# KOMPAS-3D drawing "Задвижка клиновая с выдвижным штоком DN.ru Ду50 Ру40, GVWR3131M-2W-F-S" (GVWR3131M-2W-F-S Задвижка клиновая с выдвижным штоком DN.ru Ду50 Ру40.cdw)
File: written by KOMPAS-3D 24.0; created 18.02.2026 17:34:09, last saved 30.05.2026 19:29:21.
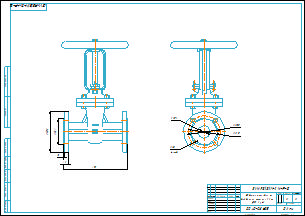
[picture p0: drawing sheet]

Document properties: art: D040-07875; Автор: R2D2; Форматы листов документа: A2; Полное имя файла: GVWR3131M-2W-F-S Задвижка клиновая с выдвижным штоком DN.ru Ду50 Ру40.m3d; Масса: 12; Наименование: Задвижка клиновая с выдвижным штоком DN.ru Ду50 Ру40; Количество листов документа: 1; Примечание: D040-08605

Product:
- Part/product: Задвижка клиновая с выдвижным штоком DN.ru Ду50 Ру40  | designation GVWR3131M-2W-F-S
    Масса: 12
    Раздел спецификации: Прочие изделия
    Примечание: D040-08605

Views: Вид 1, Спереди, Проекционный вид 2
Referenced files in E:\Работа\Зайцев\GVWR3131M-2W-F-S Задвижка клиновая с выдвижным штоком DN.ru Ду50-200 Ру63\DN50\: GVWR3131M-2W-F-S Задвижка клиновая с выдвижным штоком DN.ru Ду50 Ру63.m3d
Referenced files in E:\Работа\Зайцев\GVWR3131M-2W-F-S Задвижка клиновая с выдвижным штоком DN.ru Ду50-100 Ру40\исходные материалы\DN50\DN50\: GVWR3131M-2W-F-S Задвижка клиновая с выдвижным штоком DN.ru Ду50 Ру40.m3d
Referenced files in E:\Работа\Зайцев\Для компаса\: чертеж DN.ru.cdt
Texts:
  GVWR3131M-2W-F-S
  чертеж DN.ru.cdt
  Задвижка клиновая с
  выдвижным штоком DN.ru
  Ду50 Ру40
  Задвижка клиновая с выдвижным штоком DN.ru Ду50 Ру40
  GVWR3131M-2W-F-S Задвижка клиновая с выдвижным штоком DN.ru Ду50 Ру40
Dimensions and other numbers on the sheet: 0; 3; 2; 4; 250; 102; 160; 20; 135; 50; 18; 4 отв.; 125; 1:2; 1; 12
